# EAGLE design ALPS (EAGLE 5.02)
MFG: AVX; PN: TCJR106M006R0500
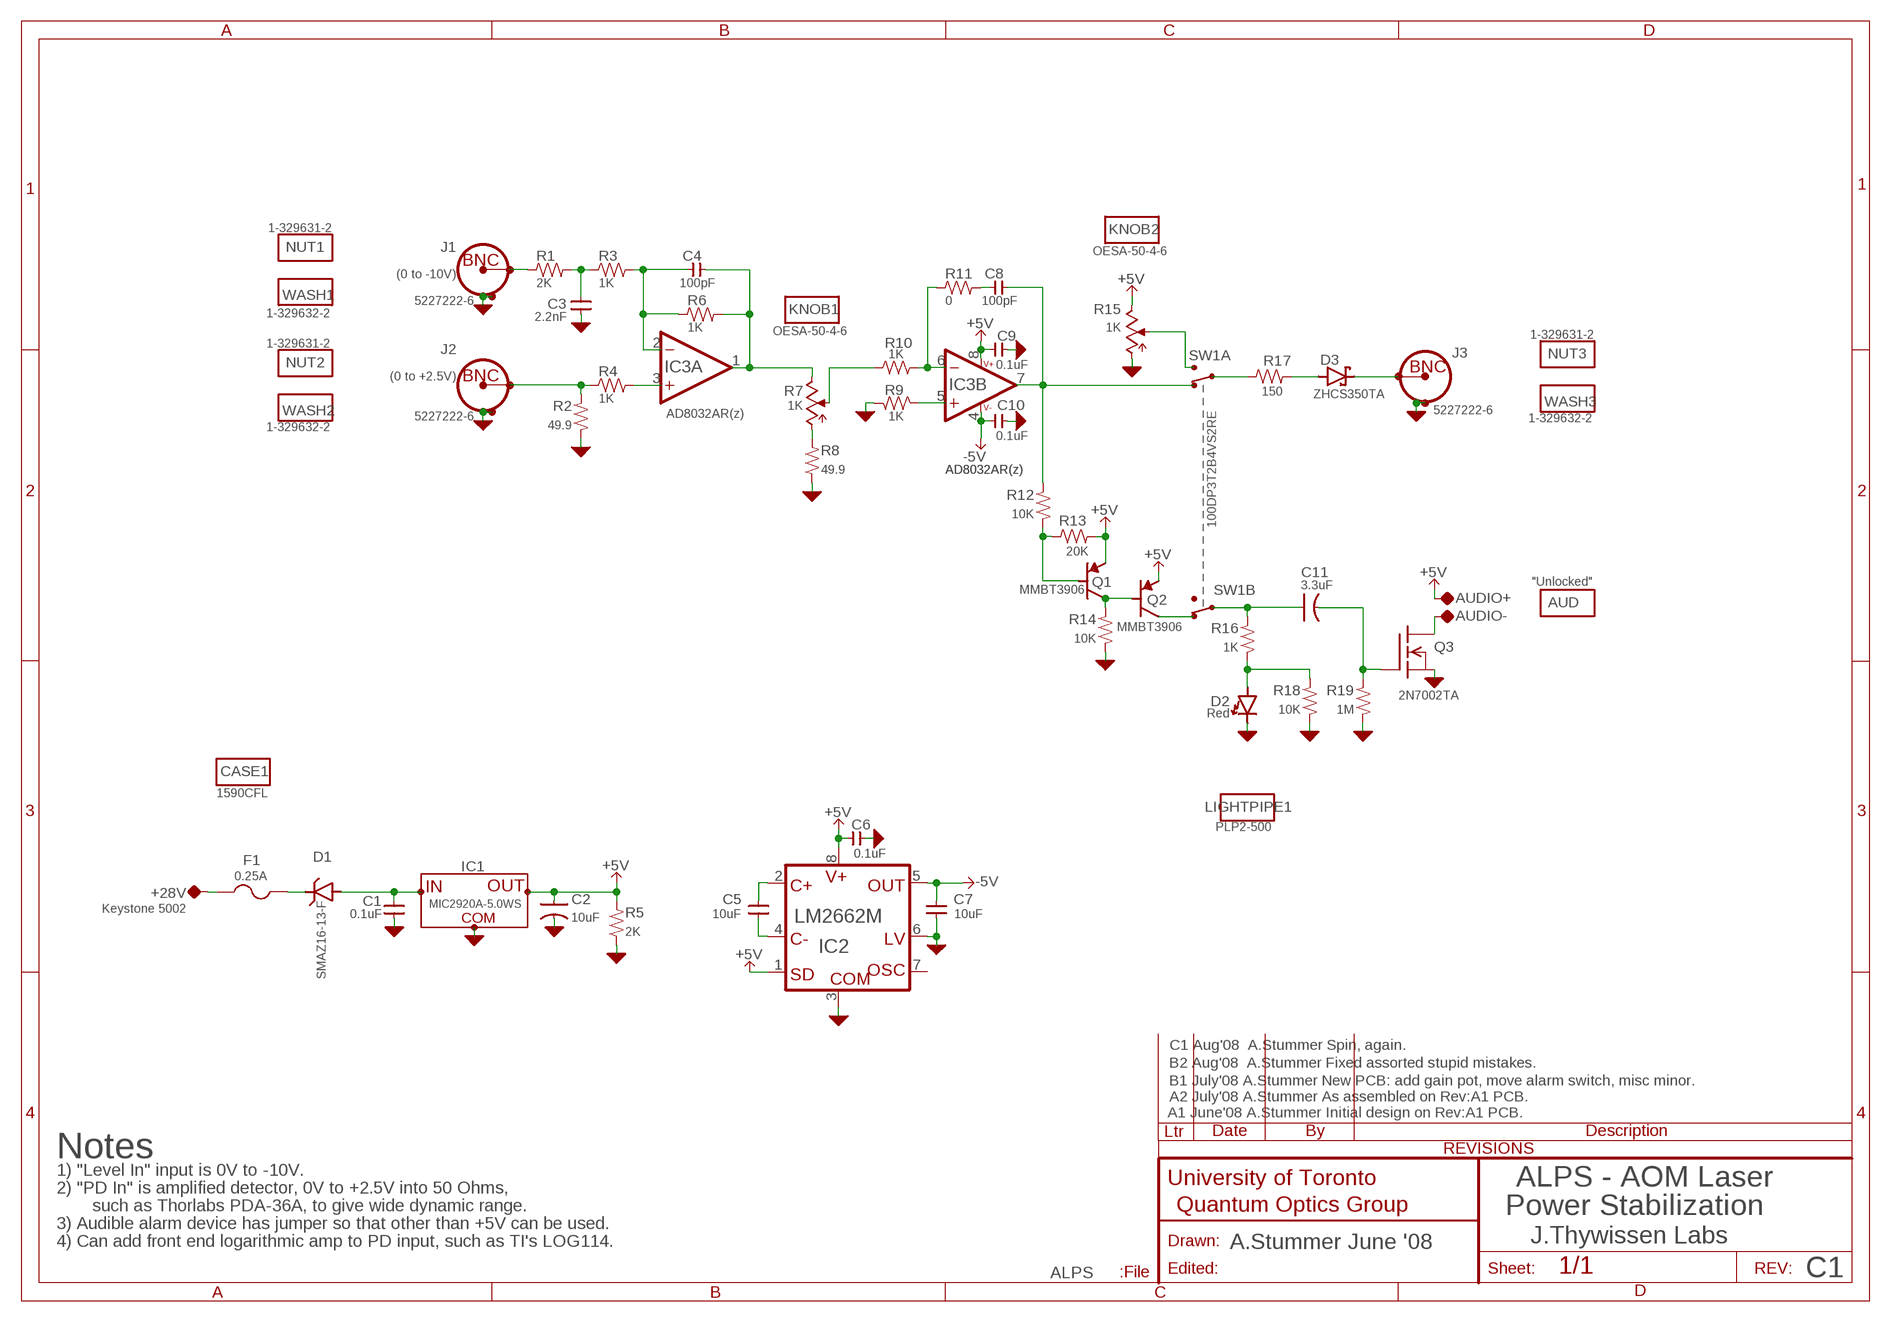
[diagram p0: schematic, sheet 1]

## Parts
+28V  Keystone 5002  TP-0.042B  [TP-0.042B]
AUD  "Unlocked"  MISC  [MISC]
AUDIO+  Keystone 5002  TP-0.042B  [TP-0.042B]
AUDIO-  Keystone 5002  TP-0.042B  [TP-0.042B]
C1  0.1uF  CAP-V-0805  [2012(0805)]
C2  10uF  CAP-POL-1206  [3216(1206)]
C3  2.2nF  CAP-V-0805  [2012(0805)]
C4  100pF  CAP-H-0805  [2012(0805)]
C5  10uF  CAP-V-0805  [2012(0805)]
C6  0.1uF  CAP-H-0805  [2012(0805)]
C7  10uF  CAP-V-0805  [2012(0805)]
C8  100pF  CAP-H-0805  [2012(0805)]
C9  0.1uF  CAP-H-0805  [2012(0805)]
C10  0.1uF  CAP-H-0805  [2012(0805)]
C11  3.3uF  CAP-POL-0805  [2012(0805)]
CASE1  1590CFL  MISC  [MISC]
D1  SMAZ16-13-F  ZENER-EIA-A  [EIA-A(SMA)]
D2  Red  LED-1209  [1209]
D3  ZHCS350TA  DIODE,SCHOTTKY-SOD523  [SOD523]
F1  0.25A  FUSE-5X20-4  [FUSE]
IC1  MIC2920A-5.0WS  78-SOT223  [SOT223]
IC2  LM2662M  LM2663M  [SOIC-8]
IC3  AD8032AR(z)  OPAMP_DUAL-SOIC8  [SOIC-8]
J1  5227222-6  CONN-BNC-TYPE1VERT  [CONN-BNC-AMP-TYPE1VERT]
J2  5227222-6  CONN-BNC-TYPE1VERT  [CONN-BNC-AMP-TYPE1VERT]
J3  5227222-6  CONN-BNC-TYPE1VERT  [CONN-BNC-AMP-TYPE1VERT]
KNOB1  OESA-50-4-6  MISC  [MISC]
KNOB2  OESA-50-4-6  MISC  [MISC]
LIGHTPIPE1  PLP2-500  MISC  [MISC]
NUT1  1-329631-2  MISC  [MISC]
NUT2  1-329631-2  MISC  [MISC]
NUT3  1-329631-2  MISC  [MISC]
Q1  MMBT3906  BJT-PNP-SOT23  [SOT23]
Q2  MMBT3906  BJT-PNP-SOT23  [SOT23]
Q3  2N7002TA  MOSFET-N-SOT23  [SOT23]
R1  2K  R-H-0805  [2012(0805)]
R2  49.9  R-V-0805  [2012(0805)]
R3  1K  R-H-0805  [2012(0805)]
R4  1K  R-H-0805  [2012(0805)]
R5  2K  R-V-0805  [2012(0805)]
R6  1K  R-H-0805  [2012(0805)]
R7  1K  POT-PRECISION_SPR_RV8  [PRECISION-SPR-RV8(POT)]
R8  49.9  R-V-0805  [2012(0805)]
R9  1K  R-V-0805  [2012(0805)]
R10  1K  R-H-0805  [2012(0805)]
R11  0  R-H-0805  [2012(0805)]
R12  10K  R-V-0805  [2012(0805)]
R13  20K  R-H-0805  [2012(0805)]
R14  10K  R-V-0805  [2012(0805)]
R15  1K  POT-PRECISION_SPR_RV8  [PRECISION-SPR-RV8(POT)]
R16  1K  R-V-0805  [2012(0805)]
R17  150  R-H-0805  [2012(0805)]
R18  10K  R-V-0805  [2012(0805)]
R19  1M  R-V-0805  [2012(0805)]
SW1  100DP3T2B4VS2RE  SWITCH_DPDT-ESWITCH_100DP?VS2  [SWITCH-ESWITCH_100DP?VS2]
WASH1  1-329632-2  MISC  [MISC]
WASH2  1-329632-2  MISC  [MISC]
WASH3  1-329632-2  MISC  [MISC]

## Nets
+5V: AUDIO+.TP C2.2(POS) C6.1 C9.1 IC1.3(OUT) IC2.1(SD) IC2.8(V+) IC3.8(.:V++) Q1.2(E) Q2.2(E) R5.2 R13.2 R15.CW
-5V: C7.2 C10.1 IC2.5(OUT) IC3.4(.:V-)
AGND: C1.1 C2.1(NEG) C3.1 C6.2 C7.1 C9.2 C10.2 D2.K(C) IC1.2@1(COM) IC2.3(COM) IC2.6(LV) J1.SHIELD1 J1.SHIELD2 J2.SHIELD1 J2.SHIELD2 J3.SHIELD1 J3.SHIELD2 Q3.2(S) R2.1 R5.1 R8.1 R9.1 R14.1 R15.CCW R18.1 R19.1
N$1: D3.C J3.CONDUCTOR
N$3: IC3.6(B:-IN) R10.2 R11.1
N$4: C8.1 R11.2
N$5: R17.1 SW1.C1(A:COM1)
N$6: R15.W SW1.NO1(A:NO1)
N$7: J1.CONDUCTOR R1.1
N$8: IC3.5(B:+IN) R9.2
N$9: Q1.3(C) Q2.1(B) R14.2
N$10: J2.CONDUCTOR R2.2 R4.1
N$11: Q1.1(B) R12.1 R13.1
N$12: C11.2(POS) R16.2 SW1.C2(B:COM1)
N$13: D2.A R16.1 R18.2
N$14: Q2.3(C) SW1.NC2(B:NC1)
N$15: C11.1(NEG) Q3.1(G) R19.2
N$16: AUDIO-.TP Q3.3(D)
N$17: C1.2 D1.1A(A) IC1.1(VI)
N$18: C5.2 IC2.2(C+)
N$19: +28V.TP F1.1A
N$20: D1.2K(C) F1.2A
N$21: C4.2 IC3.1(A:OUT) R6.2 R7.CW
N$22: C4.1 IC3.2(A:-IN) R3.2 R6.1
N$23: IC3.3(A:+IN) R4.2
N$24: R7.W R10.1
N$25: R7.CCW R8.2
N$26: C5.1 IC2.4(C-)
N$27: C3.2 R1.2 R3.1
N$28: D3.A R17.2
N$29: C8.2 IC3.7(B:OUT) R12.2 SW1.NC1(A:NC1)
Unconnected: IC2.7(OSC) SW1.NO2(B:NO1)

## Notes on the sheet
- (0 to -10V)
- (0 to +2.5V)
- C1 Aug'08  A.Stummer Spin, again.
- B2 Aug'08  A.Stummer Fixed assorted stupid mistakes.
- B1 July'08 A.Stummer New PCB: add gain pot, move alarm switch, misc minor.
- A2 July'08 A.Stummer As assembled on Rev:A1 PCB.
- A1 June'08 A.Stummer Initial design on Rev:A1 PCB.
- Notes
- 1) "Level In" input is 0V to -10V.
- ALPS - AOM Laser
- 2) "PD In" is amplified detector, 0V to +2.5V into 50 Ohms,
- such as Thorlabs PDA-36A, to give wide dynamic range. | Power Stabilization
- 3) Audible alarm device has jumper so that other than +5V can be used.
- 4) Can add front end logarithmic amp to PD input, such as TI's LOG114. | A.Stummer June '08 | J.Thywissen Labs
- C1

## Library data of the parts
+28V AUDIO+ AUDIO- = QuantumOptics:TP: Testpoint, test point on schematic, on PCB either SMT pad, small hole or loop style TP.
AUD CASE1 KNOB1 KNOB2 LIGHTPIPE1 NUT1-NUT3 WASH1-WASH3 = QuantumOptics:MISC: Miscellaneous Part, just a placeholder for miscellaeous parts
C1 C3 C5 C7 = QuantumOptics:CAP-V-: Cap, SMT and Through-hole, 0402 and up.
C2 C11 = QuantumOptics:CAP-POL-: Capacitor, Polarized, SMT 0805 and up, probably tantalum.
C4 C6 C8-C10 = QuantumOptics:CAP-H-: Cap, SMT and Through-hole, 0402 and up.
D1 = QuantumOptics:ZENER: Zener
D2 = QuantumOptics:LED: LED
D3 = QuantumOptics:DIODE,SCHOTTKY: Schottky Diode, general purpose.
F1 = QuantumOptics:FUSE: Fuse
IC1 = QuantumOptics:78*: Positive regulator, probably fixed output. E.g. SOT-223 Micrel MIC2920, http://www.micrel.com/_PDF/mic2920.pdf e.g. uA78L05ACPK, http://www-s.ti.com/sc/ds/ua78l05a.pdf
IC2 = QuantumOptics:LM2663: LM2663, switched cap DC-DC converter. Inverter, doubler, supply splitter.
IC3 = QuantumOptics:OPAMP_DUAL: Dual Op Amp, common pinouts. Based on http://www.analog.com/static/imported-files/data_sheets/AD8651_8652.pdf
J1-J3 = QuantumOptics:CONN-BNC: BNC PCB, horizontal or vertical, e.g. vertical: Amp 227677-1, nut 1-329631-2, shoulder washer 330620. The two shield connections allow the assembly on either side of the board. Horiz isolated: 5227222-6, http://catalog.tycoelectronics.com/TE/bin/TE.Connect?C=1&M=BYPN&TCPN=5227222-6&RQPN=5227222-6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; DESC: Input?
Q1 Q2 = QuantumOptics:BJT-PNP: PNP BJT, generic, p/n defined by VALUE field. E.g. Fairchild MMBT3906 (abs max 40V, 200mA. hFE>80@10mA.
Q3 = QuantumOptics:MOSFET-N: Mosfet, N-Channel, generic enhancement mode N-FET.
R1 R3 R4 R6 R10 R11 R13 R17 = QuantumOptics:R-H-*: Resistor, SMT & Through-Hole, horizontal symbol
R2 R5 R8 R9 R12 R14 R16 R18 R19 = QuantumOptics:R-V-*: Resistor, SMT & Through-Hole, vertical symbol
R7 R15 = QuantumOptics:POT: Pot, regular or trimpot
SW1 = QuantumOptics:SWITCH_DPDT: Switch, DPDT

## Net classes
0 default: width 0.203 mm, clearance 0.203 mm

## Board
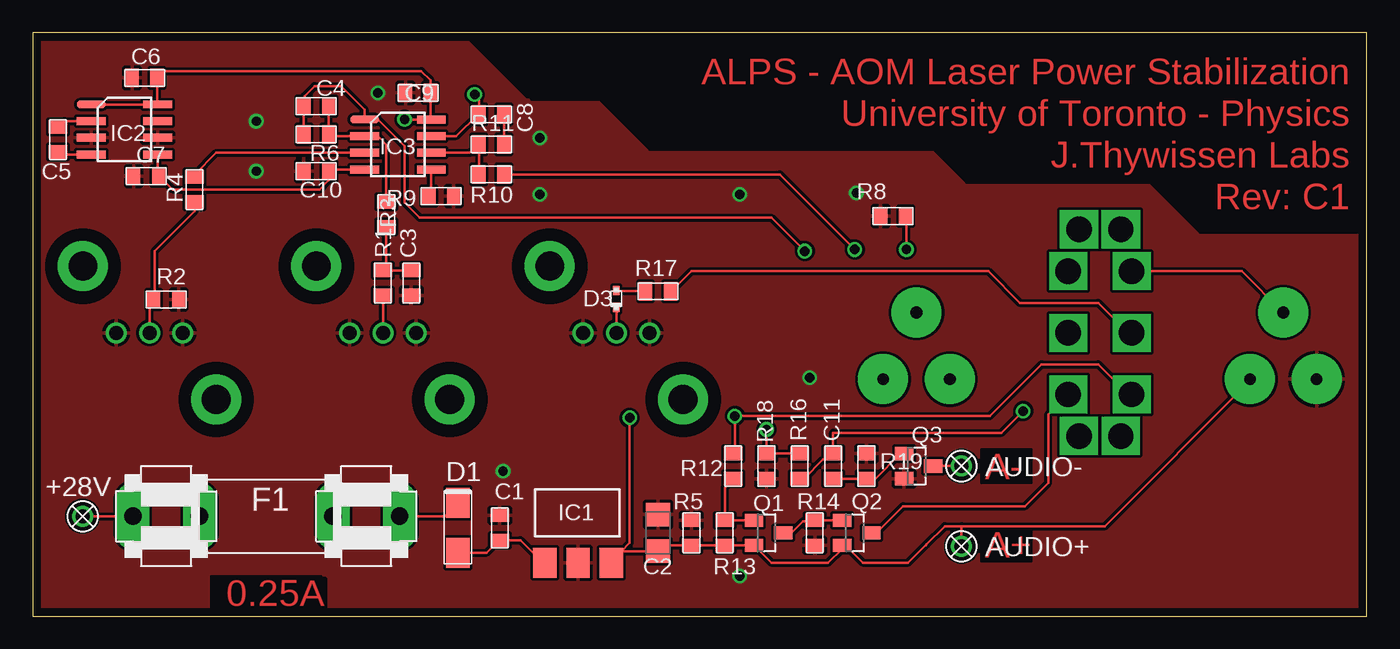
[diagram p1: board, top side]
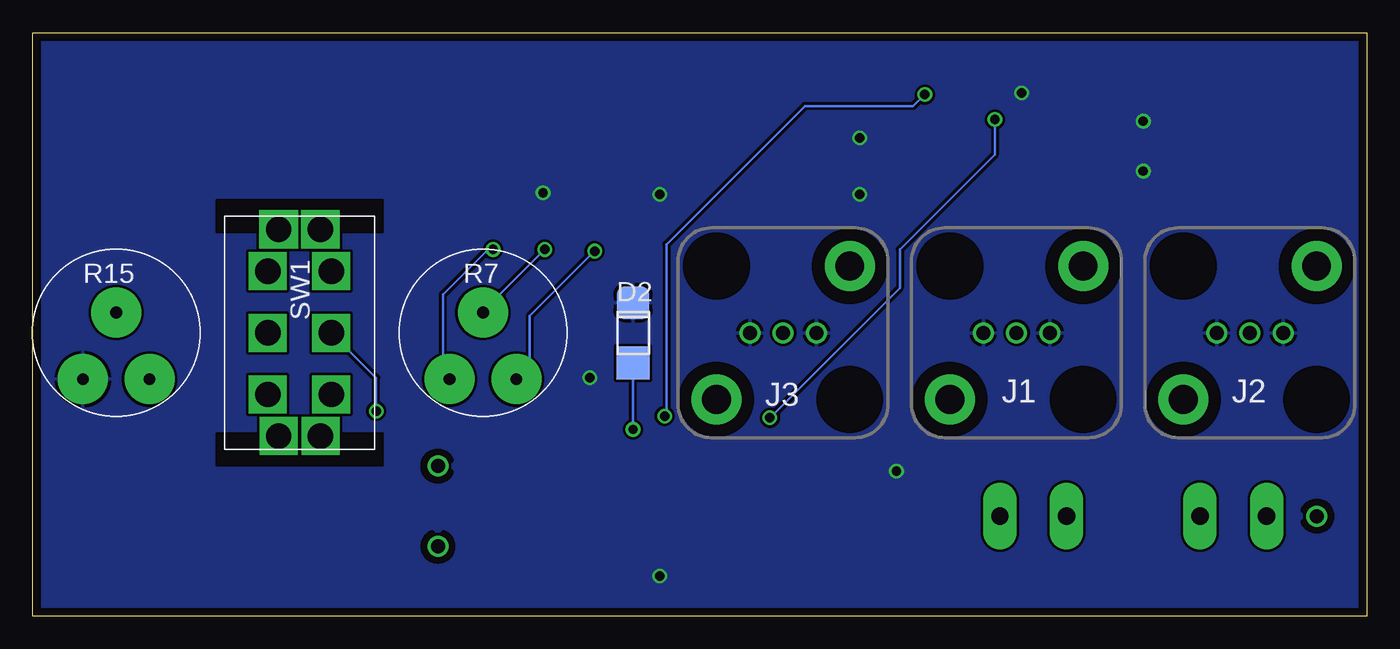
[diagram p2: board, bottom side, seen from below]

Size 101.6 x 44.45 mm. Coordinates in mm from the lower left corner, seen from the top.
Outline: 0,0 101.6,0 101.6,44.45 0,44.45 0,0
Copper layers (1*16): Top 0.035mm / dielectric 1.5mm / Bottom 0.035mm
Design rules "DRC standard check (8mil trace and gap, 20mil drill, etc) *": minimum track width 7mil, minimum drill 20mil, track to track 7mil, track to pad 7mil, pad to pad 7mil, via to via 7mil, smd to smd 7mil, copper to edge 25mil, drill to drill 8mil, minimum pad ring 10mil, minimum via ring 8mil, stop-mask expansion 4mil, vias tented up to drill 0mil, thermal gap 10mil
tRestrict: 18 lines

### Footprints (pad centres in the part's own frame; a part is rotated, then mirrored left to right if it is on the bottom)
TP-0.042B = drill 1.067 round: TP 0,0
2012(0805) = smd 1.016 x 1.397: 1 -0.953,0; 2 0.953,0
3216(1206) = smd 1.8 x 1.8: 1 -1.4,0; 2 1.4,0
EIA-A(SMA) = smd 2.3 x 1.8: 1A -1.905,0; 2K 1.905,0
1209 = smd 2.5 x 2.5: A 2.3,0; K -2.3,0
SOD523 = smd 0.7 x 0.5: A 0.67,0; C -0.6,0
FUSE = drill 1.321 pad 2.54 long: 1A -10.16,0; 1B -5.08,0; 2A 10.16,0; 2B 5.08,0
SOT223 = smd 1.778 x 2.286: 1 -2.54,-2.54; 2@1 0,-2.54; 3 2.54,-2.54
SOIC-8 = smd 0.6 x 2.2: 1 -1.27,-2.54; 2 0,-2.54; 3 1.27,-2.54; 4 2.54,-2.54; 5 2.54,2.54; 6 1.27,2.54; 7 0,2.54; 8 -1.27,2.54
CONN-BNC-AMP-TYPE1VERT = drill 1.067 round: CONDUCTOR 0,0; SHIELD1 -2.54,0; SHIELD2 2.54,0 | drill 2.184 pad 3.81 round: MTG1 -5.08,-5.08; MTG2 5.08,5.08
SOT23 = smd 1 x 1.4: 1 -0.953,-0.953; 2 0.953,-0.953; 3 0,1.27
PRECISION-SPR-RV8(POT) = drill 0.889 pad 3.81 round: CCW -2.54,-3.531; CW 2.54,-3.531; W 0,1.549
SWITCH-ESWITCH_100DP?VS2 = drill 1.93 square: C1 -2.42,0; C2 2.42,0; MTG3 1.595,-7.875; MTG4 -1.595,-7.875; NC1 -2.42,-4.7; NC2 2.42,-4.7; NO1 -2.42,4.7; NO2 2.42,4.7 | drill 1.93 pad 2.946 square: MTG1 -1.595,7.875; MTG2 1.595,7.875

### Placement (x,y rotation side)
+28V  3.81,7.62 180 top
AUD  not placed on the board
AUDIO+  70.74,5.33 270 top
AUDIO-  70.74,11.43 0 top
C1  35.56,6.73 270 top
C2  47.62,6.35 270 top
C3  28.83,25.4 90 top
C4  21.59,38.86 180 top
C5  1.91,36.32 90 top
C6  8.51,41.02 180 top
C7  8.64,33.53 0 top
C8  34.92,38.23 180 top
C9  29.34,39.88 180 top
C10  21.59,33.91 180 top
C11  60.96,11.43 90 top
CASE1  not placed on the board
D1  32.38,6.73 90 top
D2  55.88,21.59 270 bottom
D3  44.45,24.13 90 top
F1  17.78,7.62 0 top
IC1  41.53,6.6 0 top
IC2  6.99,37.72 270 top
IC3  27.81,36.58 270 top
J1  26.67,21.59 0 bottom
J2  8.89,21.59 0 bottom
J3  44.45,21.59 0 bottom
KNOB1  not placed on the board
KNOB2  not placed on the board
LIGHTPIPE1  not placed on the board
NUT1  not placed on the board
NUT2  not placed on the board
NUT3  not placed on the board
Q1  55.88,6.35 270 top
Q2  62.61,6.35 270 top
Q3  67.31,11.43 270 top
R1  26.67,25.4 90 top
R2  10.16,24.13 180 top
R3  26.92,30.61 90 top
R4  12.32,32.51 90 top
R5  50.16,6.35 270 top
R6  21.59,36.7 180 top
R7  67.31,21.59 0 bottom
R8  65.53,30.48 0 top
R9  31.11,32 180 top
R10  34.92,33.66 180 top
R11  34.92,35.94 0 top
R12  53.34,11.43 90 top
R13  52.7,6.35 270 top
R14  59.56,6.35 90 top
R15  95.25,21.59 0 bottom
R16  58.42,11.43 270 top
R17  47.62,24.77 180 top
R18  55.88,11.43 90 top
R19  63.5,11.43 270 top
SW1  81.28,21.59 0 bottom
U$18  [TITLEBLOCK_PCB]  not placed on the board
WASH1  not placed on the board
WASH2  not placed on the board
WASH3  not placed on the board

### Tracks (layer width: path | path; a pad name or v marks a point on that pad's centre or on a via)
+5V  (via drill 0.71)
  Top 0.203: IC2.1 IC2.8 9.53,38.86 9.46,38.92 C6.1 9.46,41.15 9.53,41.15 9.91,41.53 29.59,41.53 30.29,40.83 C9.1 30.29,38.16 30.35,38.1 IC3.8 v28.32,37.85 | IC1.3 44.07,4.19 44.83,4.95 | 44.83,4.95 45.47,5.59 v45.47,15.11 | R15.CW 92.71,17.91 81.66,6.86 70.74,6.86 | 70.74,6.86 AUDIO+.TP | 68.07,5.46 68.01,5.4 | 68.07,5.46 69.47,6.86 70.74,6.86 | 44.83,4.95 C2.2 48.07,5.4 R5.2 50.16,5.46 50.23,5.4 R13.2 52.7,5.46 52.77,5.4 Q1.2 54.93,5.46 54.99,5.33 56.26,4.06 60.58,4.06 61.66,5.14 Q2.2 61.91,5.4 63.25,4.06 66.67,4.06 68.07,5.46
  Bottom 0.203: v45.47,15.11 35.56,25.02 35.56,27.94 28.32,35.18 v28.32,37.85
-5V
  Top 0.203: IC2.5 9.53,33.66 9.59,33.66 C7.2 9.65,33.53 10.67,32.51 21.84,32.51 22.54,33.21 C10.1 22.48,33.91 22.61,34.04 IC3.4
AGND  (via drill 0.71)
  other vias: 17.02,33.91 17.02,37.72 38.61,36.45 38.61,32.13 53.85,32.13 59.18,18.16 62.74,32.26 35.81,11.05 53.85,3.05 26.29,39.88
  pour Top: 0,0 101.6,0 101.6,29.21 88.9,29.21 85.09,33.02 71.12,33.02 68.58,35.56 46.99,35.56 43.18,39.37 37.59,39.37 32.51,44.45 0,44.45
  pour Bottom: 0,0 101.6,0 101.6,44.45 0,44.45
N$1
  Top 0.203: J3.CONDUCTOR 44.58,21.59 44.45,21.72 D3.C
N$3
  Top 0.203: R10.2 33.97,35.88 34.04,35.94 R11.1 33.91,35.94 33.27,35.31 IC3.6
N$4
  Top 0.203: R11.2 35.81,35.94 35.88,36.01 C8.1
N$5
  Top 0.203: SW1.C1 83.44,21.59 81.15,23.88 75.18,23.88 72.77,26.29 50.16,26.29 48.64,24.77 R17.1
N$6
  Top 0.203: R15.W 95.25,23.11 92.07,26.29 SW1.NO1
N$7
  Top 0.203: J1.CONDUCTOR R1.1
N$8
  Top 0.203: R9.2 30.1,31.88 30.35,32.13 IC3.5
N$9
  Top 0.203: Q1.3 57.78,6.35 58.67,7.24 59.44,7.24 59.56,7.37 | 59.56,7.37 R14.2 | Q2.1 59.63,7.3 59.56,7.37
N$10
  Top 0.203: J2.CONDUCTOR 8.89,23.75 9.27,24.13 | R4.1 12.32,30.86 9.27,27.81 9.27,24.13 | 9.27,24.13 R2.2
N$11
  Top 0.203: Q1.1 52.77,7.3 52.7,7.24 R13.1 52.7,9.78 53.34,10.41 R12.1
N$12  (via drill 0.71)
  Top 0.203: R16.2 58.74,10.48 60.2,11.94 60.45,11.94 60.96,12.45 | 60.96,12.45 C11.2 | 60.96,12.45 60.96,13.97 73.79,13.97 v75.44,15.62
  Bottom 0.203: SW1.C2 75.44,18.16 v75.44,15.62
N$13  (via drill 0.71)
  Top 0.203: R16.1 55.94,12.38 55.88,12.45 R18.2 v55.88,14.22
  Bottom 0.203: 55.88,19.3 D2.A v55.88,14.22
N$14
  Top 0.203: Q2.3 64.26,6.35 66.29,8.38 75.56,8.38 77.34,10.16 77.34,15.37 78.74,16.76 SW1.NC2
N$15
  Top 0.203: C11.1 63.44,10.48 63.5,10.54 | Q3.1 66.1,12.38 64.14,10.41 63.63,10.41 63.5,10.54 | 63.5,10.54 R19.2
N$16
  Top 0.203: AUDIO-.TP Q3.3
N$17
  Top 0.203: D1.1A 34.54,4.83 35.56,5.84 C1.2 37.15,5.78 38.99,3.94 IC1.1
N$18
  Top 0.203: C5.2 1.91,37.21 2.41,37.72 IC2.2
N$19
  Top 0.203: +28V.TP F1.1A
N$20
  Top 0.203: F1.2A 31.37,7.62 D1.2K
N$21  (via drill 0.71)
  Top 0.203: R6.2 20.64,38.8 20.7,38.86 C4.2 20.57,38.86 20.7,38.99 20.7,39.62 21.46,40.39 23.5,40.39 25.27,38.61 IC3.1 26.29,37.85 28.32,35.81 28.32,31.5 29.46,30.35 56.26,30.35 v58.8,27.81
  Bottom 0.203: R7.CW 64.77,18.16 63.75,19.18 63.75,22.86 v58.8,27.81
N$22
  Top 0.203: C4.1 22.48,38.86 22.54,38.8 R6.1 22.48,36.7 22.61,36.58 IC3.2 26.29,36.58 26.92,35.94 R3.2
N$23
  Top 0.203: R4.2 12.32,33.66 13.97,35.31 IC3.3
N$24  (via drill 0.71)
  Top 0.203: R10.1 56.9,33.66 v62.61,27.94
  Bottom 0.203: R7.W 67.31,23.24 v62.61,27.94
N$25  (via drill 0.71)
  Top 0.203: R8.2 66.55,30.42 v66.55,27.94
  Bottom 0.203: v66.55,27.94 66.93,27.94 70.36,24.51 70.36,19.68 69.85,19.18 R7.CCW 69.85,18.03
N$26
  Top 0.203: C5.1 1.91,35.31 2.03,35.18 IC2.4
N$27
  Top 0.203: C3.2 26.73,26.35 26.67,26.29 R1.2 26.67,26.42 26.92,26.67 R3.1
N$28
  Top 0.203: D3.A 44.58,24.89 44.7,24.77 R17.2
N$29  (via drill 0.71)
  Top 0.203: IC3.7 32.26,36.58 33.91,38.23 C8.2 33.97,39.43 v33.66,39.75 | SW1.NC1 83.44,16.89 81.15,19.18 76.83,19.18 72.9,15.24 v53.47,15.24 53.47,12.57 53.34,12.45 R12.2 53.34,12.32
  Bottom 0.203: v33.66,39.75 34.54,38.86 42.8,38.86 53.34,28.32 53.34,15.24 v53.47,15.24

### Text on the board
Top: ALPS - AOM Laser Power Stabilization | University of Toronto - Physics | J.Thywissen Labs | Rev: C1 | A- | A+ | 0.25A
Document: A. Stummer July'08 | C1 | 0.2mm(0.008") | 0.2mm(0.008") | 0.2mm(0.008") | 0.125mm(0.005") | 0.125mm(0.005") | Following are misc parts: | C1 Aug'08 A.Stummer Spin, again. | B2 Aug'08 A.Stummer As assembled on Rev:B1 PCB. | B1 July'08 A.Stummer Redesign. | A2 July'08 A.Stummer As assembled on Rev:A1 PCB. | A1 June'08 A.Stummer Initial design on Rev:A1 PCB.
Text: ALPS - AOM Laser | Power Stabilization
